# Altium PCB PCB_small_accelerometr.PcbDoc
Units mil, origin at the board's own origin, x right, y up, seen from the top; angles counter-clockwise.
Board outline 866.14 x 708.66 mil, 2 copper layers (M1(Top_copper), M2(Bottom copper), stack 12.8 mil thick; 12 components, 6 nets, 31 pads, 0 vias.
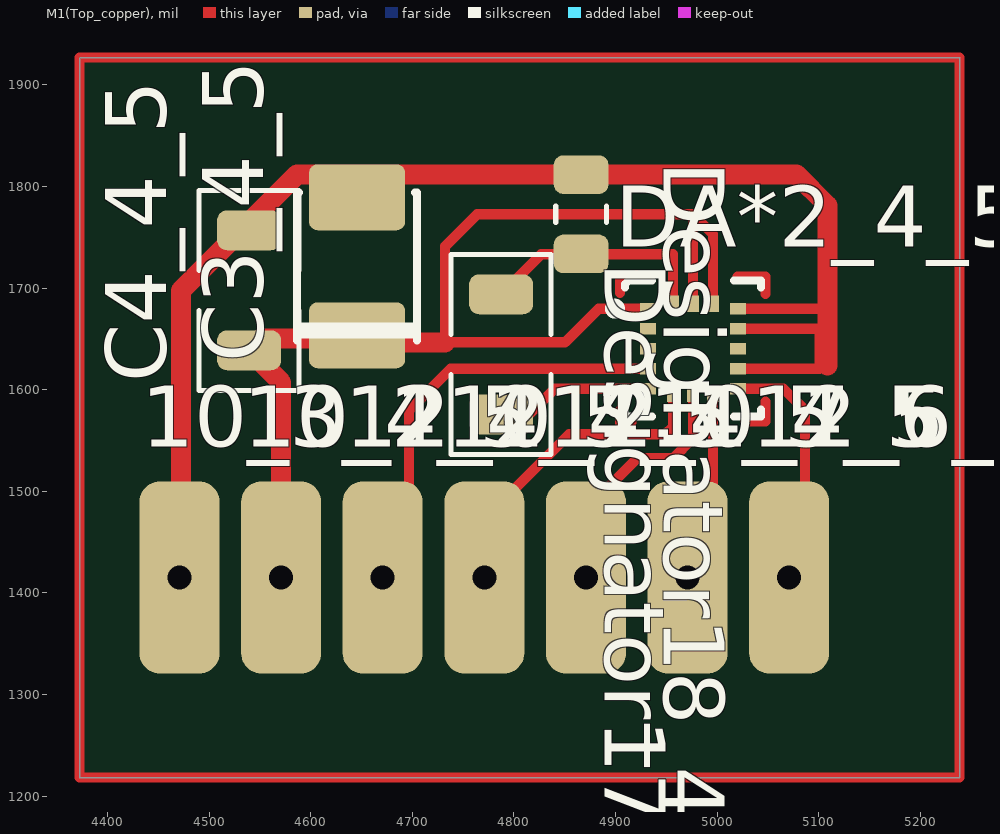
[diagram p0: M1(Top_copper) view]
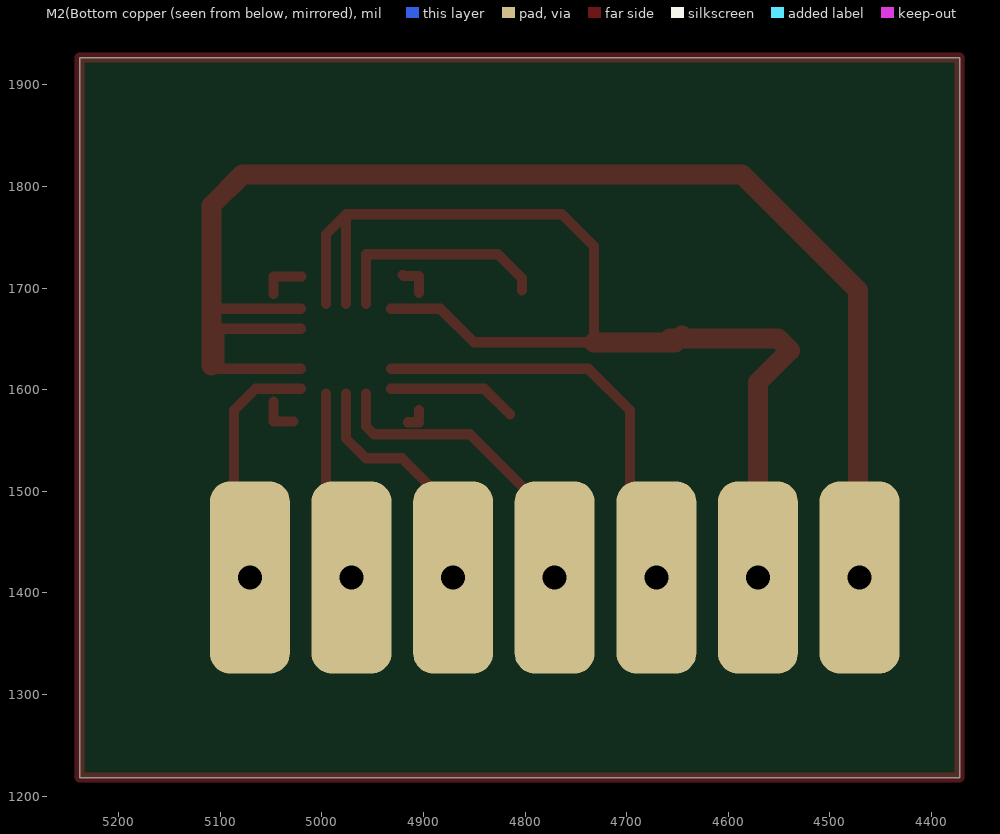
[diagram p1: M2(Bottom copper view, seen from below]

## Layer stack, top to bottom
Top Solder: solder mask 0.4, Solder Resist, Dk 3.5
M1(Top_copper): signal copper 1.4
Dielectric 1: core 10, FR-4, Dk 4.2
M2(Bottom copper: signal copper 1.4
Bottom Solder: solder mask 0.4, Solder Resist, Dk 3.5

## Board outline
4372.44,1218.31 4372.44,1926.97 5238.58,1926.97 5238.58,1218.31

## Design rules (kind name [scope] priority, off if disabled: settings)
AssemblyTestPointUsage [All] p1 off:
AssemblyTestpoint [All] p1 off: testpointundercomponent=TRUE minsize=40 maxsize=100 preferedsize=60 minholesize=0 maxholesize=40 preferedholesize=32 testpointgrid=1 usegrid=TRUE gridtolerance=0.01 allowsidetop=TRUE allowsidebottom=TRUE
Clearance Clearance_GND [All vs InNet('No Net')] p1: gap=10 except(19.68: Arc-Poly Track-Poly SMDPad-Poly THPad-Poly Via-Poly Fill-Poly Poly-Poly; 27.56: Arc-Region Track-Region SMDPad-Region THPad-Region Via-Region Fill-Region Poly-Region Region-Region)
Clearance isairon_rule [All] p2: gap=10 // Для изучения
Clearance [All] p3: gap=10 except(19.68: Arc-Poly Track-Poly SMDPad-Poly THPad-Poly Via-Poly Fill-Poly Poly-Poly; 27.56: Arc-Region Track-Region SMDPad-Region THPad-Region Via-Region Fill-Region Poly-Region Region-Region)
ComponentClearance [All] p1: gap=19.68 collisioncheckmode=3 verticalgap=19.68 showdistances=FALSE
FabricationTestPointUsage [All] p1 off: valid=0 allowmultiple=FALSE
FabricationTestpoint [All] p1 off: side=3 testpointundercomponent=TRUE minsize=40 maxsize=100 preferedsize=60 minholesize=0 maxholesize=40 preferedholesize=32 testpointgrid=1 allowsidetop=TRUE allowsidebottom=TRUE usegrid=TRUE gridtolerance=0.01
PasteMaskExpansion [All] p1 off: expansion=0
PolygonConnect [All] p1: connectstyle=Relief reliefconductorwidth=10 reliefentries=4 polygonreliefangle="90 Angle" airgapwidth=10
RoutingVias [All] p1: holewidth=23.62 width=82.68 viastyle="Through Hole" minholewidth=19.68 minwidth=74.8 maxholewidth=59.06 maxwidth=86.61
SolderMaskExpansion [All] p1 off: expansion=4
Width [All] p1: maxlimit=39.37 minlimit=10 preferedwidth=19.68
24 further rules are at their usual default settings.

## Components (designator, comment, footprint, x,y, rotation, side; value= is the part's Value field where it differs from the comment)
10_1_4_5 "FAT_single_BLC_pin" Single_BLC_fat_Pin 4770.87,1415.16 r0 top (schematic designator 10)
10_2_4_5 "FAT_single_BLC_pin" Single_BLC_fat_Pin 4570.87,1415.16 r0 top (schematic designator 10)
10_3_4_5 "FAT_single_BLC_pin" Single_BLC_fat_Pin 4470.87,1415.16 r0 top (schematic designator 10)
10_7_5 "FAT_single_BLC_pin" Single_BLC_fat_Pin 4970.87,1415.16 r0 top (schematic designator 10)
12_1_4_5 "FAT_single_BLC_pin" Single_BLC_fat_Pin 4870.87,1415.16 r0 top (schematic designator 12)
12_2_4_5 "FAT_single_BLC_pin" Single_BLC_fat_Pin 4670.87,1415.16 r0 top (schematic designator 12)
12_6_5 "FAT_single_BLC_pin" Single_BLC_fat_Pin 5070.87,1415.16 r0 top (schematic designator 12)
C3_4_5 "10u" "EL Case B (3528-21)" 4645.67,1721.46 r90 top (schematic designator C3)
C4_4_5 "100n" C1206(3216) 4539.37,1697.83 r90 top (schematic designator C4)
DA*2_4_5 "LIS331DL" LGA-16 4976.22,1640.35 r0 top (schematic designator DA*2)
Designator17_4_5 "Comment" C1206(3216) 4787.4,1634.84 r270 top
Designator18_4_5 "Comment" 0805 4866.14,1772.64 r270 top

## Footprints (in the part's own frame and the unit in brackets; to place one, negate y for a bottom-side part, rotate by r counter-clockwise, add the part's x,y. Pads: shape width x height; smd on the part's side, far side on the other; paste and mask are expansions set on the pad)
0805 [mil] "Metal Electrode Face (MELF) Resistor; Body 2 x 1.4 mm (LxDia)"
  rrect50% 38x54 smd: 1(-39,0) 2(39,0)
  silkscreen extent -8,-25 8,25, body extent -39,-25 39,25, height 19
C1206(3216) [mm]
  rrect50% 1x1.6 smd: 1(-1.5,0) 2(1.5,0)
  silkscreen extent -2.5,-1.25 2.5,1.25, body extent -1.6,-0.8 1.6,0.8, height 1
"EL Case B (3528-21)" [mm] "Capacitor, SM Tantalum; Body 3.5 x 2.8 mm (LxW typ)"
  rrect25% 1.65x2.4 smd: 1(-1.725,0) 2(1.725,0)
  silkscreen extent -1.85,-1.5 1.85,1.5, body extent -1.75,-1.4 1.75,1.4, height 1.91
LGA-16 [mm] "LCC, 16-Pins, Body 3,00x3,00mmx1,00mm, Pitch 0,50mm, IPC Medium Density"
  rect 0.41x0.29 smd: 1(-1.125,1) 2(-1.125,0.5) 3(-1.125,0) 4(-1.125,-0.5) 5(-1.125,-1) 9(1.125,-1) 10(1.125,-0.5) 11(1.125,0) 12(1.125,0.5) 13(1.125,1)
  rect 0.29x0.41 smd: 6(-0.5,-1.125) 7(0,-1.125) 8(0.5,-1.125) 14(0.5,1.125) 15(0,1.125) 16(-0.5,1.125)
  silkscreen extent -2.07,-1.7 1.7,1.7, body extent -1.5,-1.5 1.5,1.5, height 1
Single_BLC_fat_Pin [mm]
  rrect50% 2x4.8 hole 0.6: 0(0,0)

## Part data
C3_4_5: library part "EL 10u/20V Tant.", "Case B (3528-21)"
C4_4_5: library part C_1206, "SMD-0805 50V Y5V +80/-20%"
DA*2_4_5: "MEMS motion sensor"

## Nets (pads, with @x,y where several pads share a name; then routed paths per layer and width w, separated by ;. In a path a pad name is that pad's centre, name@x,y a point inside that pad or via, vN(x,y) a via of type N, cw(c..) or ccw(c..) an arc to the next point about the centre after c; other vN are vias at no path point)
GND: 
INT2_1: 
Net12_0: 
SCK: 
SDI: 
VCC: 
pads on no net: 10_1_4_5.0 10_2_4_5.0 10_3_4_5.0 10_7_5.0 12_1_4_5.0 12_2_4_5.0 12_6_5.0 C3_4_5.1 C3_4_5.2 C4_4_5.1 C4_4_5.2 DA*2_4_5.1 DA*2_4_5.2 DA*2_4_5.3 DA*2_4_5.4 DA*2_4_5.5 DA*2_4_5.6 DA*2_4_5.7 DA*2_4_5.8 DA*2_4_5.9 DA*2_4_5.10 DA*2_4_5.11 DA*2_4_5.12 DA*2_4_5.13 DA*2_4_5.14 DA*2_4_5.15 DA*2_4_5.16 Designator17_4_5.1 Designator17_4_5.2 Designator18_4_5.1 Designator18_4_5.2
copper on no net: | length 7312.2
  M1(Top_copper) w10: 4696.85,1481.3 4696.85,1579.72 4737.8,1620.67 4931.93,1620.67 ; 4763.78,1347.44 4791.34,1375 ; 4779.53,1481.3 4854.33,1556.1 4948.82,1556.1 4956.54,1563.82 4956.54,1596.06 ; 4803.15,1697.83 4803.15,1709.65 4826.77,1733.27 4956.69,1733.27 4956.69,1684.8 4956.54,1684.65 ; 4814.96,1575.79 4840.16,1600.98 4931.93,1600.98 ; 4885.83,1497.05 4921.26,1532.48 4934.06,1532.48 4951.77,1532.48 4956.69,1532.48 4976.22,1552.01 4976.22,1596.06 ; 4904.43,1568.06 4915.43,1568.06 ; 4904.43,1573.06 4904.43,1580.06 ; 4904.43,1695.06 4904.43,1712.06 4919.43,1712.06 4920.43,1713.06 ; 4931.93,1679.72 4883.46,1679.72 4850.39,1646.65 4732.28,1646.65 4732.28,1741.14 4763.78,1772.64 4976.22,1772.64 ; 4976.22,1684.65 4976.22,1772.64 ; 4995.91,1596.06 4995.91,1481.46 5000,1477.36 ; 4995.91,1684.65 4995.91,1752.95 4976.22,1772.64 ; 5020.05,1711.43 5047.61,1711.43 5047.61,1694.06 ; 5020.51,1600.98 5065.35,1600.98 5086.61,1579.72 5086.61,1477.36 ; 5020.51,1620.67 5100.79,1620.67 5100.79,1660.04 5020.51,1660.04 ; 5020.51,1679.72 5108.66,1679.72 ; 5027.92,1568.7 5047.61,1568.7 5047.61,1588.39 ; 4372.44,1218.31 5238.58,1218.31 5238.58,1926.97 4372.44,1926.97 4372.44,1218.31
  M1(Top_copper) w19.68: 4472.44,1449.8 4472.44,1697.83 4586.61,1812.01 5077.95,1812.01 5108.66,1781.3 5108.66,1623.82 ; 4570.87,1415.16 4570.87,1607.28 4539.37,1638.78 4551.18,1650.59 4657.48,1650.59 ; 4645.67,1653.54 4652.56,1646.65 4732.28,1646.65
